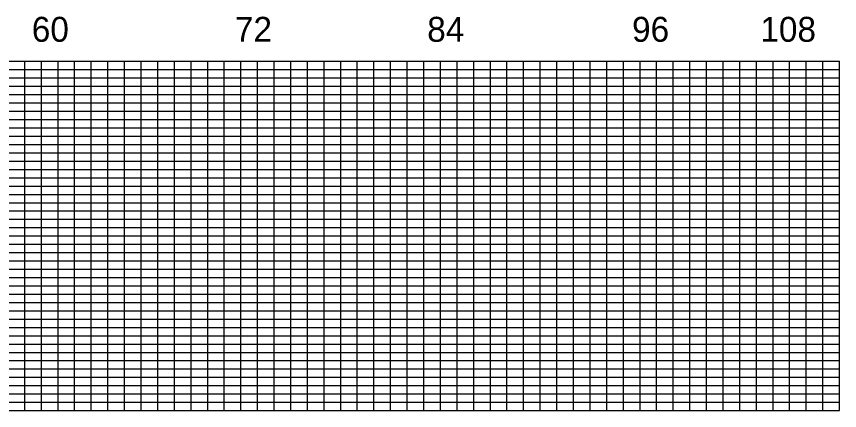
# Model space of a CAD drawing. Extents: x 1873632 to 1926512, y 813126 to 836257.
# Drawn here: x 1886538 to 1889013, y 820525 to 821710 of the extents above; entities that cross this region are included whole.
import ezdxf

# ---------------------------------------------------------------- set-up
doc = ezdxf.new("R2010")
doc.units = 0
doc.layers.add('RD_PD_WallFill', color=7, linetype='Continuous')

msp = doc.modelspace()

# ---------------------------------------------------------------- linework, layer by layer
at = {"layer": 'RD_PD_WallFill'}
for p, q in [((1883663.1, 821575.1), (1889013.1, 821575.1)), ((1886563.1, 820525.1), (1886563.1, 821575.1)), ((1886563.1, 820525.1), (1886563.1, 821575.1)), ((1886613.1, 820525.1), (1886613.1, 821575.1)), ((1886613.1, 820525.1), (1886613.1, 821575.1)), ((1886663.1, 820525.1), (1886663.1, 821575.1)), ((1886663.1, 820525.1), (1886663.1, 821575.1)), ((1886713.1, 820525.1), (1886713.1, 821575.1)), ((1886713.1, 820525.1), (1886713.1, 821575.1)), ((1886763.1, 820525.1), (1886763.1, 821575.1)), ((1886763.1, 820525.1), (1886763.1, 821575.1)), ((1886813.1, 820525.1), (1886813.1, 821575.1)), ((1886813.1, 820525.1), (1886813.1, 821575.1)), ((1886863.1, 820525.1), (1886863.1, 821575.1)), ((1886863.1, 820525.1), (1886863.1, 821575.1)), ((1886913.1, 820525.1), (1886913.1, 821575.1)), ((1886913.1, 820525.1), (1886913.1, 821575.1)), ((1886963.1, 820525.1), (1886963.1, 821575.1)), ((1886963.1, 820525.1), (1886963.1, 821575.1)), ((1887013.1, 820525.1), (1887013.1, 821575.1)), ((1887013.1, 820525.1), (1887013.1, 821575.1)), ((1887063.1, 820525.1), (1887063.1, 821575.1)), ((1887063.1, 820525.1), (1887063.1, 821575.1)), ((1887113.1, 820525.1), (1887113.1, 821575.1)), ((1887113.1, 820525.1), (1887113.1, 821575.1)), ((1887163.1, 820525.1), (1887163.1, 821575.1)), ((1887163.1, 820525.1), (1887163.1, 821575.1)), ((1887213.1, 820525.1), (1887213.1, 821575.1)), ((1887213.1, 820525.1), (1887213.1, 821575.1)), ((1887263.1, 820525.1), (1887263.1, 821575.1)), ((1887263.1, 820525.1), (1887263.1, 821575.1)), ((1887313.1, 820525.1), (1887313.1, 821575.1)), ((1887313.1, 820525.1), (1887313.1, 821575.1)), ((1887363.1, 820525.1), (1887363.1, 821575.1)), ((1887363.1, 820525.1), (1887363.1, 821575.1)), ((1887413.1, 820525.1), (1887413.1, 821575.1)), ((1887413.1, 820525.1), (1887413.1, 821575.1)), ((1887463.1, 820525.1), (1887463.1, 821575.1)), ((1887463.1, 820525.1), (1887463.1, 821575.1)), ((1887513.1, 820525.1), (1887513.1, 821575.1)), ((1887513.1, 820525.1), (1887513.1, 821575.1)), ((1887563.1, 820525.1), (1887563.1, 821575.1)), ((1887563.1, 820525.1), (1887563.1, 821575.1)), ((1887613.1, 820525.1), (1887613.1, 821575.1)), ((1887613.1, 820525.1), (1887613.1, 821575.1)), ((1887663.1, 820525.1), (1887663.1, 821575.1)), ((1887663.1, 820525.1), (1887663.1, 821575.1)), ((1887713.1, 820525.1), (1887713.1, 821575.1)), ((1887713.1, 820525.1), (1887713.1, 821575.1)), ((1887763.1, 820525.1), (1887763.1, 821575.1)), ((1887763.1, 820525.1), (1887763.1, 821575.1)), ((1887813.1, 820525.1), (1887813.1, 821575.1)), ((1887813.1, 820525.1), (1887813.1, 821575.1)), ((1887863.1, 820525.1), (1887863.1, 821575.1)), ((1887863.1, 820525.1), (1887863.1, 821575.1)), ((1887913.1, 820525.1), (1887913.1, 821575.1)), ((1887913.1, 820525.1), (1887913.1, 821575.1)), ((1887963.1, 820525.1), (1887963.1, 821575.1)), ((1887963.1, 820525.1), (1887963.1, 821575.1)), ((1888013.1, 820525.1), (1888013.1, 821575.1)), ((1888013.1, 820525.1), (1888013.1, 821575.1)), ((1888063.1, 820525.1), (1888063.1, 821575.1)), ((1888063.1, 820525.1), (1888063.1, 821575.1)), ((1888113.1, 820525.1), (1888113.1, 821575.1)), ((1888113.1, 820525.1), (1888113.1, 821575.1)), ((1888163.1, 820525.1), (1888163.1, 821575.1)), ((1888163.1, 820525.1), (1888163.1, 821575.1)), ((1888213.1, 820525.1), (1888213.1, 821575.1)), ((1888213.1, 820525.1), (1888213.1, 821575.1)), ((1888263.1, 820525.1), (1888263.1, 821575.1)), ((1888263.1, 820525.1), (1888263.1, 821575.1)), ((1888313.1, 820525.1), (1888313.1, 821575.1)), ((1888313.1, 820525.1), (1888313.1, 821575.1)), ((1888363.1, 820525.1), (1888363.1, 821575.1)), ((1888363.1, 820525.1), (1888363.1, 821575.1)), ((1888413.1, 820525.1), (1888413.1, 821575.1)), ((1888413.1, 820525.1), (1888413.1, 821575.1)), ((1888463.1, 820525.1), (1888463.1, 821575.1)), ((1888463.1, 820525.1), (1888463.1, 821575.1)), ((1888513.1, 820525.1), (1888513.1, 821575.1)), ((1888513.1, 820525.1), (1888513.1, 821575.1)), ((1888563.1, 820525.1), (1888563.1, 821575.1)), ((1888563.1, 820525.1), (1888563.1, 821575.1)), ((1888613.1, 820525.1), (1888613.1, 821575.1)), ((1888613.1, 820525.1), (1888613.1, 821575.1)), ((1888663.1, 820525.1), (1888663.1, 821575.1)), ((1888663.1, 820525.1), (1888663.1, 821575.1)), ((1888713.1, 820525.1), (1888713.1, 821575.1)), ((1888713.1, 820525.1), (1888713.1, 821575.1)), ((1888763.1, 820525.1), (1888763.1, 821575.1)), ((1888763.1, 820525.1), (1888763.1, 821575.1)), ((1888813.1, 820525.1), (1888813.1, 821575.1)), ((1888813.1, 820525.1), (1888813.1, 821575.1)), ((1888863.1, 820525.1), (1888863.1, 821575.1)), ((1888863.1, 820525.1), (1888863.1, 821575.1)), ((1888913.1, 820525.1), (1888913.1, 821575.1)), ((1888913.1, 820525.1), (1888913.1, 821575.1)), ((1888963.1, 820525.1), (1888963.1, 821575.1)), ((1888963.1, 820525.1), (1888963.1, 821575.1)), ((1889013.1, 820525.1), (1889013.1, 821575.1)), ((1889013.1, 820525.1), (1889013.1, 821575.1)), ((1884113.1, 821550.1), (1889013.1, 821550.1)), ((1884113.1, 821550.1), (1889013.1, 821550.1)), ((1884113.1, 821525.1), (1889013.1, 821525.1)), ((1884113.1, 821500.1), (1889013.1, 821500.1)), ((1884113.1, 821475.1), (1889013.1, 821475.1)), ((1884113.1, 821450.1), (1889013.1, 821450.1)), ((1883663.1, 821425.1), (1889013.1, 821425.1)), ((1883663.1, 821400.1), (1889013.1, 821400.1)), ((1883663.1, 821375.1), (1889013.1, 821375.1)), ((1883663.1, 821350.1), (1889013.1, 821350.1)), ((1883663.1, 821325.1), (1889013.1, 821325.1)), ((1883663.1, 821300.1), (1889013.1, 821300.1)), ((1883663.1, 821275.1), (1889013.1, 821275.1)), ((1883663.1, 821250.1), (1889013.1, 821250.1)), ((1883663.1, 821225.1), (1889013.1, 821225.1)), ((1883663.1, 821200.1), (1889013.1, 821200.1)), ((1883663.1, 821175.1), (1889013.1, 821175.1)), ((1883663.1, 821150.1), (1889013.1, 821150.1)), ((1883663.1, 821125.1), (1889013.1, 821125.1)), ((1883663.1, 821100.1), (1889013.1, 821100.1)), ((1883663.1, 821075.1), (1889013.1, 821075.1)), ((1883663.1, 821050.1), (1889013.1, 821050.1)), ((1883663.1, 821025.1), (1889013.1, 821025.1)), ((1883663.1, 821000.1), (1889013.1, 821000.1)), ((1883663.1, 820975.1), (1889013.1, 820975.1)), ((1883663.1, 820950.1), (1889013.1, 820950.1)), ((1883663.1, 820925.1), (1889013.1, 820925.1)), ((1883663.1, 820900.1), (1889013.1, 820900.1)), ((1883663.1, 820875.1), (1889013.1, 820875.1)), ((1883663.1, 820850.1), (1889013.1, 820850.1)), ((1883663.1, 820825.1), (1889013.1, 820825.1)), ((1883663.1, 820800.1), (1889013.1, 820800.1)), ((1883663.1, 820775.1), (1889013.1, 820775.1)), ((1883663.1, 820750.1), (1889013.1, 820750.1)), ((1883663.1, 820725.1), (1889013.1, 820725.1)), ((1883663.1, 820700.1), (1889013.1, 820700.1)), ((1883663.1, 820675.1), (1889013.1, 820675.1)), ((1883663.1, 820650.1), (1889013.1, 820650.1)), ((1883663.1, 820625.1), (1889013.1, 820625.1)), ((1883663.1, 820600.1), (1889013.1, 820600.1)), ((1883663.1, 820575.1), (1889013.1, 820575.1)), ((1883663.1, 820550.1), (1889013.1, 820550.1)), ((1883663.1, 820525.1), (1889013.1, 820525.1)), ((1883663.1, 820525.1), (1889013.1, 820525.1))]:
    msp.add_line(p, q, dxfattribs=at)

# ---------------------------------------------------------------- texts
for s, p in [('60', (1886584.2, 821633.8)), ('60', (1886584.2, 821633.8)), ('72', (1887194.9, 821633.8)), ('72', (1887194.9, 821633.8)), ('84', (1887773.2, 821633.8)), ('84', (1887773.2, 821633.8)), ('96', (1888389.2, 821633.8)), ('96', (1888389.2, 821633.8)), ('108', (1888775, 821633.8))]:
    msp.add_text(s, height=75, dxfattribs=at).set_placement(p)

doc.saveas('drawing.dxf')
